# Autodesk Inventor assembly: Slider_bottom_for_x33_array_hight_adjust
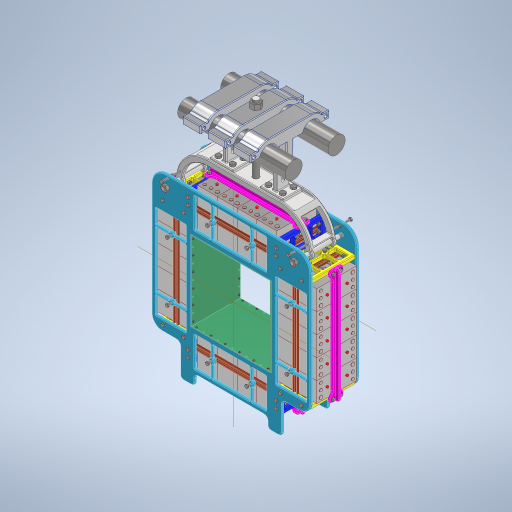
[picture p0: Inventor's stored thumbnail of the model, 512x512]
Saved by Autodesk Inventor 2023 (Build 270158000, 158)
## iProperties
Created: 2022-09
Part Number: Slider_bottom_for_x33_array_hight_adjust
Material: Aluminum 6061
Document SubType Name: Modeling
Designer: tornqvih
Mass: 680.873 g
Surface Area: 393.631 cm^2
Volume: 252.175 cm^3
Density: 2.7 g/cm^3
Appearance: Default
Sending System: Autodesk Inventor 2021
Preprocessor: ST-DEVELOPER v18.1
Title: C:\Users\Oleksii\Documents\Inventor\Scintillators_for_ISS\Part\ISSKUL9_v2.stp
Author: Oleksii
Part Number: Slider_bottom_for_x33_array
Mass: 854.06 g
Surface Area: 503.636 cm^2
Volume: 316.319 cm^3
Title: C:\Users\Oleksii\Documents\Inventor\Scintillators_for_ISS\Part\ISSKUL8_v2.stp
Created: 2023-10
Part Number: CeBr3Holder4x5
Document SubType Name: Assembly
Mass: 44866.1 g
Surface Area: 24623.5 cm^2
Volume: 16659.9 cm^3
Density: 2.69305 g/cm^3
Author: tornqvih
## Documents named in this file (31)
- \\Mac\Home\Documents\chalmers\Inventor2023\CeBr3Holder4x5\CeBr3Holder4x5.iam
- \\Mac\Home\Documents\chalmers\Inventor2023\CeBr3Holder4x5\FrontPlate.ipt
- \\Mac\Home\Documents\chalmers\Inventor2023\CeBr3Holder4x5\ShieldTop.ipt
- \\Mac\Home\Documents\chalmers\Inventor2023\CeBr3Holder4x5\ShieldLeft.ipt
- \\Mac\Home\Documents\chalmers\Inventor2023\CeBr3Holder4x5\SupportHorizontal.ipt
- \\Mac\Home\Documents\chalmers\Inventor2023\CeBr3Holder4x5\SupportVertical.ipt
- \\Mac\Home\Documents\chalmers\Inventor2023\CeBr3Holder4x5\BarHorizontal.ipt
- \\Mac\Home\Documents\chalmers\Inventor2023\CeBr3Holder4x5\BarVertical.ipt
- \\Mac\Home\Documents\chalmers\Inventor2023\CeBr3Holder4x5\CeBr3.ipt
- **\\Mac\Home\Documents\chalmers\Inventor2023\CeBr3Holder4x5\CeBr3Holder4x5.iam*LocalDocs*xAaaaqoaaAaaaaaaaAaaaqnqtPb*ISSKUL8_v2.ipt
- **\\Mac\Home\Documents\chalmers\Inventor2023\CeBr3Holder4x5\CeBr3Holder4x5.iam*LocalDocs*xAaaaarbaAaaaaaaaAaaaqtyoWc*ISSKUL9_v2.ipt
- \\Mac\Home\Documents\chalmers\Inventor2023\CeBr3Holder4x5\HangerSlide.ipt
- \\Mac\Home\Documents\chalmers\Inventor2023\CeBr3Holder4x5\ThreadedRod.ipt
- \\Mac\Home\Documents\Inventor\Content Center Files\R2023\en-US\AS 1112 (2)\AS 1112 - M10  Type 5.ipt
- \\Mac\Home\Documents\chalmers\Inventor2023\CeBr3Holder4x5\Roller.ipt
- \\Mac\Home\Documents\chalmers\Inventor2023\CeBr3Holder4x5\ThreadedHeight.ipt
- \\Mac\Home\Documents\Inventor\Content Center Files\R2023\en-US\AS 1112 (2)\AS 1112 - M16  Type 5.ipt
- \\Mac\Home\Documents\chalmers\Inventor2023\CeBr3Holder4x5\Hanger.ipt
- \\Mac\Home\Documents\chalmers\Inventor2023\CeBr3Holder4x5\U4.ipt
- \\Mac\Home\Documents\chalmers\Inventor2023\CeBr3Holder4x5\U5.ipt
- \\Mac\Home\Documents\chalmers\Inventor2023\CeBr3Holder4x5\U2.ipt
- \\Mac\Home\Documents\Inventor\Content Center Files\R2023\en-US\AS 1110\AS 1110 - M5 x 25.ipt
- \\Mac\Home\Documents\Inventor\Content Center Files\R2023\en-US\AS 1112 (2)\AS 1112 - M5  Type 5.ipt
- \\Mac\Home\Documents\Inventor\Content Center Files\R2023\en-US\AS 1427(05)\AS 1427 - M2.5 x 8(5) II.ipt
- \\Mac\Home\Documents\Inventor\Content Center Files\R2023\en-US\AS 1110\AS 1110 - M5 x 50.ipt
- \\Mac\Home\Documents\Inventor\Content Center Files\R2023\en-US\AS 1110\AS 1110 - M5 x 35.ipt
- \\Mac\Home\Documents\Inventor\Content Center Files\R2023\en-US\AS 1110\AS 1110 - M8 x 50.ipt
- \\Mac\Home\Documents\Inventor\Content Center Files\R2023\en-US\AS 1110\AS 1110 - M8 x 35.ipt
- \\Mac\Home\Documents\Inventor\Content Center Files\R2023\en-US\AS 1112 (2)\AS 1112 - M8  Type 5.ipt
- \\Mac\Home\Documents\chalmers\Inventor2023\ISSKUL_v2\ISSKUL8_v2.stp
- \\Mac\Home\Documents\chalmers\Inventor2023\ISSKUL_v2\ISSKUL9_v2.stp
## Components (281 placed, 47 different names)
1. FrontPlate
2. BackPlate
3. ShieldTop
4. ShieldBottom
5. ShieldLeft
6. ShieldRight
7. SupportHorizontalTR
8. SupportHorizontalTL
9. SupportHorizontalBL
10. SupportHorizontalBR
11. SupportVerticalTR
12. SupportVerticalTL
13. SupportVerticalBL
14. SupportVerticalBR
15. BarHorizontalTop — Mate:351, Mate:375, Mate:376
16. BarHorizontalBottom — Mate:350, Mate:377, Mate:378
17. BarVerticalRight — Mate:356, Mate:379, Mate:380
18. BarVerticalLeft — Mate:359, Mate:381, Mate:382
19. CeBr3:1 — Mate:138, Mate:139, Mate:140, Mate:143, Mate:151, Mate:351
20. CeBr3:2 — Mate:141, Mate:142, Mate:143, Mate:146, Mate:154
21. CeBr3:3 — Mate:144, Mate:145, Mate:146, Mate:149, Mate:157
22. CeBr3:4 — Mate:147, Mate:148, Mate:149, Mate:160, Mate:399
23. CeBr3:5 — Mate:150, Mate:151, Mate:152, Mate:155, Mate:391
24. CeBr3:6 — Mate:153, Mate:154, Mate:155, Mate:158
25. CeBr3:7 — Mate:156, Mate:157, Mate:158, Mate:161
26. CeBr3:8 — Mate:159, Mate:160, Mate:161
27. CeBr3:9 — Mate:162, Mate:163, Mate:164, Mate:167, Mate:175
28. CeBr3:10 — Mate:165, Mate:166, Mate:167, Mate:170, Mate:178
29. CeBr3:11 — Mate:168, Mate:169, Mate:170, Mate:173, Mate:181
30. CeBr3:12 — Mate:171, Mate:172, Mate:173, Mate:184, Mate:401
31. CeBr3:13 — Mate:174, Mate:175, Mate:176, Mate:179, Mate:393
32. CeBr3:14 — Mate:177, Mate:178, Mate:179, Mate:182
33. CeBr3:15 — Mate:180, Mate:181, Mate:182, Mate:185
34. CeBr3:16 — Mate:183, Mate:184, Mate:185, Mate:350
35. CeBr3:17 — Mate:186, Mate:187, Mate:188, Mate:191, Mate:202, Mate:359
36. CeBr3:18 — Mate:189, Mate:190, Mate:191, Mate:194, Mate:205
37. CeBr3:19 — Mate:192, Mate:193, Mate:194, Mate:197, Mate:208
38. CeBr3:20 — Mate:195, Mate:196, Mate:197, Mate:200, Mate:211
39. CeBr3:21 — Mate:198, Mate:199, Mate:200, Mate:214, Mate:405
40. CeBr3:22 — Mate:201, Mate:202, Mate:203, Mate:206, Mate:397
41. CeBr3:23 — Mate:204, Mate:205, Mate:206, Mate:209
42. CeBr3:24 — Mate:207, Mate:208, Mate:209, Mate:212
43. CeBr3:25 — Mate:210, Mate:211, Mate:212, Mate:215
44. CeBr3:26 — Mate:213, Mate:214, Mate:215
45. CeBr3:27 — Mate:216, Mate:217, Mate:218, Mate:221, Mate:232, Mate:356
46. CeBr3:28 — Mate:219, Mate:220, Mate:221, Mate:224, Mate:235
47. CeBr3:29 — Mate:222, Mate:223, Mate:224, Mate:227, Mate:238
48. CeBr3:30 — Mate:225, Mate:226, Mate:227, Mate:230, Mate:241
49. CeBr3:31 — Mate:228, Mate:229, Mate:230, Mate:244, Mate:403
50. CeBr3:32 — Mate:231, Mate:232, Mate:233, Mate:236, Mate:395
51. CeBr3:33 — Mate:234, Mate:235, Mate:236, Mate:239
52. CeBr3:34 — Mate:237, Mate:238, Mate:239, Mate:242
53. CeBr3:35 — Mate:240, Mate:241, Mate:242, Mate:245
54. CeBr3:36 — Mate:243, Mate:244, Mate:245
55. ThreadedRodRight — Mate:316, Flush:314, Mate:383, Angle:2
56. ThreadedRodLeft — Mate:317, Flush:315, Mate:384, Angle:3
57. AS 1112 (2) - Metric M10  Type 5:1
58. AS 1112 (2) - Metric M10  Type 5:2
59. AS 1112 (2) - Metric M10  Type 5:3
60. AS 1112 (2) - Metric M10  Type 5:4
61. Hanger:1
62. HangerSlideRight
63. HangerSlideLeft
64. ISSKUL8_v2:1 — Mate:315, Mate:334, Mate:338, Flush:316, Mate:341, Flush:317
65. ISSKUL8_v2:2 — Mate:314, Mate:333, Mate:336, Mate:339
66. ISSKUL9_v2:1 — Mate:337, Mate:340, Mate:373
67. RollerFront
68. RollerBack — Mate:339, Mate:340, Mate:341, Flush:317, Angle:1, Mate:362
69. ThreadedHeight:1 — Mate:373, Mate:388
70. U4Top — Mate:391, Mate:392, Mate:408, Mate:416, Mate:439, Mate:440
71. U4Bottom — Mate:393, Mate:394, Mate:410, Mate:422, Mate:445, Mate:446
72. U5Right — Mate:395, Mate:396, Mate:412, Mate:420, Mate:443, Mate:444
73. U5Left — Mate:397, Mate:398, Mate:414, Mate:418, Mate:441, Mate:442
74. U2Top — Mate:399, Mate:400, Mate:424, Mate:426, Mate:447, Mate:448
75. U2Bottom — Mate:401, Mate:402, Mate:436, Mate:438, Mate:449, Mate:450
76. U2Right — Mate:403, Mate:404, Mate:428, Mate:430, Mate:451, Mate:452
77. U2Left — Mate:405, Mate:406, Mate:432, Mate:434, Mate:453, Mate:454
78. AS 1110 - Metric M5 x 25:1
79. AS 1110 - Metric M5 x 25:12
80. AS 1110 - Metric M5 x 25:13
81. AS 1110 - Metric M5 x 25:14
82. AS 1110 - Metric M5 x 25:15
83. AS 1110 - Metric M5 x 25:16
84. AS 1110 - Metric M5 x 25:17
85. AS 1110 - Metric M5 x 25:18
86. AS 1110 - Metric M5 x 25:19
87. AS 1110 - Metric M5 x 25:20
88. AS 1110 - Metric M5 x 25:21
89. AS 1110 - Metric M5 x 25:22
90. AS 1110 - Metric M5 x 25:23
91. AS 1110 - Metric M5 x 25:24
92. AS 1110 - Metric M5 x 25:25
93. AS 1110 - Metric M5 x 25:26
94. AS 1110 - Metric M5 x 25:27
95. AS 1110 - Metric M5 x 25:38
96. AS 1110 - Metric M5 x 25:39
97. AS 1110 - Metric M5 x 25:40
98. AS 1110 - Metric M5 x 25:41
99. AS 1110 - Metric M5 x 25:42
100. AS 1110 - Metric M5 x 25:43
101. AS 1110 - Metric M5 x 25:44
102. AS 1110 - Metric M5 x 25:45
103. AS 1110 - Metric M5 x 25:46
104. AS 1110 - Metric M5 x 25:47
105. AS 1110 - Metric M5 x 25:48
106. AS 1110 - Metric M5 x 25:49
107. AS 1110 - Metric M5 x 25:50
108. AS 1110 - Metric M5 x 25:51
109. AS 1110 - Metric M5 x 25:52
110. AS 1112 (2) - Metric M5  Type 5:1
111. AS 1112 (2) - Metric M5  Type 5:2
112. AS 1112 (2) - Metric M5  Type 5:3
113. AS 1112 (2) - Metric M5  Type 5:4
114. AS 1112 (2) - Metric M5  Type 5:5
115. AS 1112 (2) - Metric M5  Type 5:6
116. AS 1112 (2) - Metric M5  Type 5:7
117. AS 1112 (2) - Metric M5  Type 5:8
118. AS 1112 (2) - Metric M5  Type 5:9
119. AS 1112 (2) - Metric M5  Type 5:10
120. AS 1112 (2) - Metric M5  Type 5:11
121. AS 1112 (2) - Metric M5  Type 5:12
122. AS 1112 (2) - Metric M5  Type 5:13
123. AS 1112 (2) - Metric M5  Type 5:14
124. AS 1112 (2) - Metric M5  Type 5:15
125. AS 1112 (2) - Metric M5  Type 5:16
126. AS 1112 (2) - Metric M5  Type 5:17
127. AS 1112 (2) - Metric M5  Type 5:18
128. AS 1112 (2) - Metric M5  Type 5:19
129. AS 1112 (2) - Metric M5  Type 5:20
130. AS 1112 (2) - Metric M5  Type 5:21
131. AS 1112 (2) - Metric M5  Type 5:22
132. AS 1112 (2) - Metric M5  Type 5:23
133. AS 1112 (2) - Metric M5  Type 5:24
134. AS 1112 (2) - Metric M5  Type 5:25
135. AS 1112 (2) - Metric M5  Type 5:26
136. AS 1112 (2) - Metric M5  Type 5:27
137. AS 1112 (2) - Metric M5  Type 5:28
138. AS 1112 (2) - Metric M5  Type 5:29
139. AS 1112 (2) - Metric M5  Type 5:30
140. AS 1112 (2) - Metric M5  Type 5:31
141. AS 1112 (2) - Metric M5  Type 5:32
142. AS 1427 H - Metric M2.5 x 8:1
143. AS 1427 H - Metric M2.5 x 8:2
144. AS 1427 H - Metric M2.5 x 8:3
145. AS 1427 H - Metric M2.5 x 8:4
146. AS 1427 H - Metric M2.5 x 8:5
147. AS 1427 H - Metric M2.5 x 8:6
148. AS 1427 H - Metric M2.5 x 8:7
149. AS 1427 H - Metric M2.5 x 8:8
150. AS 1427 H - Metric M2.5 x 8:9
151. AS 1427 H - Metric M2.5 x 8:10
152. AS 1427 H - Metric M2.5 x 8:11
153. AS 1427 H - Metric M2.5 x 8:12
154. AS 1427 H - Metric M2.5 x 8:13
155. AS 1427 H - Metric M2.5 x 8:14
156. AS 1427 H - Metric M2.5 x 8:15
157. AS 1427 H - Metric M2.5 x 8:16
158. AS 1427 H - Metric M2.5 x 8:17
159. AS 1427 H - Metric M2.5 x 8:18
160. AS 1427 H - Metric M2.5 x 8:19
161. AS 1427 H - Metric M2.5 x 8:20
162. AS 1427 H - Metric M2.5 x 8:21
163. AS 1427 H - Metric M2.5 x 8:22
164. AS 1427 H - Metric M2.5 x 8:23
165. AS 1427 H - Metric M2.5 x 8:24
166. AS 1427 H - Metric M2.5 x 8:25
167. AS 1427 H - Metric M2.5 x 8:26
168. AS 1427 H - Metric M2.5 x 8:27
169. AS 1427 H - Metric M2.5 x 8:28
170. AS 1427 H - Metric M2.5 x 8:29
171. AS 1427 H - Metric M2.5 x 8:30
172. AS 1427 H - Metric M2.5 x 8:31
173. AS 1427 H - Metric M2.5 x 8:32
174. AS 1427 H - Metric M2.5 x 8:33
175. AS 1427 H - Metric M2.5 x 8:34
176. AS 1427 H - Metric M2.5 x 8:35
177. AS 1427 H - Metric M2.5 x 8:36
178. AS 1427 H - Metric M2.5 x 8:37
179. AS 1427 H - Metric M2.5 x 8:38
180. AS 1427 H - Metric M2.5 x 8:39
181. AS 1427 H - Metric M2.5 x 8:40
182. AS 1427 H - Metric M2.5 x 8:41
183. AS 1427 H - Metric M2.5 x 8:42
184. AS 1427 H - Metric M2.5 x 8:43
185. AS 1427 H - Metric M2.5 x 8:44
186. AS 1427 H - Metric M2.5 x 8:45
187. AS 1427 H - Metric M2.5 x 8:46
188. AS 1427 H - Metric M2.5 x 8:47
189. AS 1427 H - Metric M2.5 x 8:48
190. AS 1110 - Metric M5 x 50:1 — Mate:455, Mate:456
191. AS 1110 - Metric M5 x 50:2 — Mate:457, Mate:458
192. AS 1110 - Metric M5 x 50:3 — Mate:459, Mate:460
193. AS 1110 - Metric M5 x 50:4 — Mate:461, Mate:462
194. AS 1110 - Metric M5 x 25:53 — Mate:407, Mate:408
195. AS 1110 - Metric M5 x 25:54 — Mate:409, Mate:410
196. AS 1110 - Metric M5 x 25:55 — Mate:411, Mate:412
197. AS 1110 - Metric M5 x 25:56 — Mate:413, Mate:414
198. AS 1110 - Metric M5 x 25:57 — Mate:415, Mate:416
199. AS 1110 - Metric M5 x 25:58 — Mate:417, Mate:418
200. AS 1110 - Metric M5 x 25:59 — Mate:419, Mate:420
201. AS 1110 - Metric M5 x 25:60 — Mate:421, Mate:422
202. AS 1110 - Metric M5 x 25:61 — Mate:424
203. AS 1110 - Metric M5 x 25:62 — Mate:425, Mate:426
204. AS 1110 - Metric M5 x 25:63 — Mate:427, Mate:428
205. AS 1110 - Metric M5 x 25:64 — Mate:429, Mate:430
206. AS 1110 - Metric M5 x 25:65 — Mate:431, Mate:432
207. AS 1110 - Metric M5 x 25:66 — Mate:433, Mate:434
208. AS 1110 - Metric M5 x 25:67 — Mate:435, Mate:436
209. AS 1110 - Metric M5 x 25:68 — Mate:437, Mate:438
210. AS 1112 (2) - Metric M5  Type 5:33 — Mate:439
211. AS 1112 (2) - Metric M5  Type 5:34 — Mate:440
212. AS 1112 (2) - Metric M5  Type 5:35 — Mate:443
213. AS 1112 (2) - Metric M5  Type 5:36 — Mate:444
214. AS 1112 (2) - Metric M5  Type 5:37 — Mate:441
215. AS 1112 (2) - Metric M5  Type 5:38 — Mate:442
216. AS 1112 (2) - Metric M5  Type 5:39 — Mate:445
217. AS 1112 (2) - Metric M5  Type 5:40 — Mate:446
218. AS 1112 (2) - Metric M5  Type 5:41 — Mate:447
219. AS 1112 (2) - Metric M5  Type 5:42 — Mate:448
220. AS 1112 (2) - Metric M5  Type 5:43 — Mate:451
221. AS 1112 (2) - Metric M5  Type 5:44 — Mate:452
222. AS 1112 (2) - Metric M5  Type 5:45 — Mate:453
223. AS 1112 (2) - Metric M5  Type 5:46 — Mate:454
224. AS 1112 (2) - Metric M5  Type 5:47 — Mate:450
225. AS 1112 (2) - Metric M5  Type 5:48 — Mate:449
226. AS 1110 - Metric M5 x 35:1
227. AS 1110 - Metric M5 x 35:2
228. AS 1110 - Metric M5 x 35:3
229. AS 1110 - Metric M5 x 35:4
230. AS 1110 - Metric M5 x 35:5
231. AS 1110 - Metric M5 x 35:6
232. AS 1110 - Metric M5 x 35:7
233. AS 1110 - Metric M5 x 35:8
234. AS 1110 - Metric M5 x 35:9
235. AS 1110 - Metric M5 x 35:10
236. AS 1110 - Metric M5 x 35:11
237. AS 1110 - Metric M5 x 35:12
238. AS 1110 - Metric M5 x 35:13
239. AS 1110 - Metric M5 x 35:14
240. AS 1110 - Metric M5 x 35:15
241. AS 1110 - Metric M5 x 35:16
242. AS 1112 (2) - Metric M5  Type 5:49
243. AS 1112 (2) - Metric M5  Type 5:50
244. AS 1112 (2) - Metric M5  Type 5:51
245. AS 1112 (2) - Metric M5  Type 5:52
246. AS 1112 (2) - Metric M5  Type 5:53
247. AS 1112 (2) - Metric M5  Type 5:54
248. AS 1112 (2) - Metric M5  Type 5:55
249. AS 1112 (2) - Metric M5  Type 5:56
250. AS 1112 (2) - Metric M5  Type 5:57
251. AS 1112 (2) - Metric M5  Type 5:58
252. AS 1112 (2) - Metric M5  Type 5:59
253. AS 1112 (2) - Metric M5  Type 5:60
254. AS 1112 (2) - Metric M5  Type 5:61
255. AS 1112 (2) - Metric M5  Type 5:62
256. AS 1112 (2) - Metric M5  Type 5:63
257. AS 1112 (2) - Metric M5  Type 5:64
258. AS 1112 (2) - Metric M5  Type 5:65
259. AS 1112 (2) - Metric M5  Type 5:66
260. AS 1112 (2) - Metric M5  Type 5:67
261. AS 1112 (2) - Metric M5  Type 5:68
262. AS 1110 - Metric M8 x 50:1
263. AS 1110 - Metric M8 x 50:2
264. AS 1110 - Metric M8 x 35:1
265. AS 1110 - Metric M8 x 35:2
266. AS 1110 - Metric M8 x 35:3
267. AS 1110 - Metric M8 x 35:4
268. AS 1110 - Metric M8 x 35:5
269. AS 1110 - Metric M8 x 35:6
270. AS 1110 - Metric M8 x 35:7
271. AS 1110 - Metric M8 x 35:8
272. AS 1112 (2) - Metric M8  Type 5:1
273. AS 1112 (2) - Metric M8  Type 5:2
274. AS 1112 (2) - Metric M8  Type 5:3
275. AS 1112 (2) - Metric M8  Type 5:4
276. AS 1112 (2) - Metric M8  Type 5:5
277. AS 1112 (2) - Metric M8  Type 5:6
278. AS 1112 (2) - Metric M8  Type 5:7
279. AS 1112 (2) - Metric M8  Type 5:8
280. AS 1112 (2) - Metric M16  Type 5:1
281. AS 1112 (2) - Metric M16  Type 5:2
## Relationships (215: Mate 208, Flush 4, Angle 3)
- Mate:138: CeBr3:1
- Mate:139: CeBr3:1
- Mate:140: CeBr3:1
- Mate:141: CeBr3:2
- Mate:142: CeBr3:2
- Mate:143: CeBr3:1 ↔ CeBr3:2
- Mate:144: CeBr3:3
- Mate:145: CeBr3:3
- Mate:146: CeBr3:2 ↔ CeBr3:3
- Mate:147: CeBr3:4
- Mate:148: CeBr3:4
- Mate:149: CeBr3:3 ↔ CeBr3:4
- Mate:150: CeBr3:5
- Mate:151: CeBr3:1 ↔ CeBr3:5
- Mate:152: CeBr3:5
- Mate:153: CeBr3:6
- Mate:154: CeBr3:2 ↔ CeBr3:6
- Mate:155: CeBr3:5 ↔ CeBr3:6
- Mate:156: CeBr3:7
- Mate:157: CeBr3:3 ↔ CeBr3:7
- Mate:158: CeBr3:6 ↔ CeBr3:7
- Mate:159: CeBr3:8
- Mate:160: CeBr3:4 ↔ CeBr3:8
- Mate:161: CeBr3:7 ↔ CeBr3:8
- Mate:162: CeBr3:9
- Mate:163: CeBr3:9
- Mate:164: CeBr3:9
- Mate:165: CeBr3:10
- Mate:166: CeBr3:10
- Mate:167: CeBr3:9 ↔ CeBr3:10
- Mate:168: CeBr3:11
- Mate:169: CeBr3:11
- Mate:170: CeBr3:10 ↔ CeBr3:11
- Mate:171: CeBr3:12
- Mate:172: CeBr3:12
- Mate:173: CeBr3:11 ↔ CeBr3:12
- Mate:174: CeBr3:13
- Mate:175: CeBr3:9 ↔ CeBr3:13
- Mate:176: CeBr3:13
- Mate:177: CeBr3:14
- Mate:178: CeBr3:10 ↔ CeBr3:14
- Mate:179: CeBr3:13 ↔ CeBr3:14
- Mate:180: CeBr3:15
- Mate:181: CeBr3:11 ↔ CeBr3:15
- Mate:182: CeBr3:14 ↔ CeBr3:15
- Mate:183: CeBr3:16
- Mate:184: CeBr3:12 ↔ CeBr3:16
- Mate:185: CeBr3:15 ↔ CeBr3:16
- Mate:186: CeBr3:17
- Mate:187: CeBr3:17
- Mate:188: CeBr3:17
- Mate:189: CeBr3:18
- Mate:190: CeBr3:18
- Mate:191: CeBr3:17 ↔ CeBr3:18
- Mate:192: CeBr3:19
- Mate:193: CeBr3:19
- Mate:194: CeBr3:18 ↔ CeBr3:19
- Mate:195: CeBr3:20
- Mate:196: CeBr3:20
- Mate:197: CeBr3:19 ↔ CeBr3:20
- Mate:198: CeBr3:21
- Mate:199: CeBr3:21
- Mate:200: CeBr3:20 ↔ CeBr3:21
- Mate:201: CeBr3:22
- Mate:202: CeBr3:17 ↔ CeBr3:22
- Mate:203: CeBr3:22
- Mate:204: CeBr3:23
- Mate:205: CeBr3:18 ↔ CeBr3:23
- Mate:206: CeBr3:22 ↔ CeBr3:23
- Mate:207: CeBr3:24
- Mate:208: CeBr3:19 ↔ CeBr3:24
- Mate:209: CeBr3:23 ↔ CeBr3:24
- Mate:210: CeBr3:25
- Mate:211: CeBr3:20 ↔ CeBr3:25
- Mate:212: CeBr3:24 ↔ CeBr3:25
- Mate:213: CeBr3:26
- Mate:214: CeBr3:21 ↔ CeBr3:26
- Mate:215: CeBr3:25 ↔ CeBr3:26
- Mate:216: CeBr3:27
- Mate:217: CeBr3:27
- Mate:218: CeBr3:27
- Mate:219: CeBr3:28
- Mate:220: CeBr3:28
- Mate:221: CeBr3:27 ↔ CeBr3:28
- Mate:222: CeBr3:29
- Mate:223: CeBr3:29
- Mate:224: CeBr3:28 ↔ CeBr3:29
- Mate:225: CeBr3:30
- Mate:226: CeBr3:30
- Mate:227: CeBr3:29 ↔ CeBr3:30
- Mate:228: CeBr3:31
- Mate:229: CeBr3:31
- Mate:230: CeBr3:30 ↔ CeBr3:31
- Mate:231: CeBr3:32
- Mate:232: CeBr3:27 ↔ CeBr3:32
- Mate:233: CeBr3:32
- Mate:234: CeBr3:33
- Mate:235: CeBr3:28 ↔ CeBr3:33
- Mate:236: CeBr3:32 ↔ CeBr3:33
- Mate:237: CeBr3:34
- Mate:238: CeBr3:29 ↔ CeBr3:34
- Mate:239: CeBr3:33 ↔ CeBr3:34
- Mate:240: CeBr3:35
- Mate:241: CeBr3:30 ↔ CeBr3:35
- Mate:242: CeBr3:34 ↔ CeBr3:35
- Mate:243: CeBr3:36
- Mate:244: CeBr3:31 ↔ CeBr3:36
- Mate:245: CeBr3:35 ↔ CeBr3:36
- Mate:314: ISSKUL8_v2:2
- Mate:315: ISSKUL8_v2:1
- Mate:316: ThreadedRodRight
- Flush:314: ThreadedRodRight
- Mate:317: ThreadedRodLeft
- Flush:315: ThreadedRodLeft
- Mate:333: ISSKUL8_v2:2
- Mate:334: ISSKUL8_v2:1
- Mate:336: ISSKUL8_v2:2
- Mate:337: ISSKUL9_v2:1
- Mate:338: ISSKUL8_v2:1
- Flush:316: ISSKUL8_v2:1
- Mate:339: ISSKUL8_v2:2 ↔ RollerBack
- Mate:340: ISSKUL9_v2:1 ↔ RollerBack
- Mate:341: ISSKUL8_v2:1 ↔ RollerBack
- Flush:317: ISSKUL8_v2:1 ↔ RollerBack
- Mate:350: BarHorizontalBottom ↔ CeBr3:16
- Mate:351: BarHorizontalTop ↔ CeBr3:1
- Mate:356: BarVerticalRight ↔ CeBr3:27
- Mate:359: BarVerticalLeft ↔ CeBr3:17
- Angle:1: RollerBack
- Mate:362: RollerBack
- Mate:373: ISSKUL9_v2:1 ↔ ThreadedHeight:1
- Mate:375: BarHorizontalTop
- Mate:376: BarHorizontalTop
- Mate:377: BarHorizontalBottom
- Mate:378: BarHorizontalBottom
- Mate:379: BarVerticalRight
- Mate:380: BarVerticalRight
- Mate:381: BarVerticalLeft
- Mate:382: BarVerticalLeft
- Mate:383: ThreadedRodRight
- Mate:384: ThreadedRodLeft
- Mate:388: ThreadedHeight:1
- Angle:2: ThreadedRodRight
- Angle:3: ThreadedRodLeft
- Mate:391: CeBr3:5 ↔ U4Top
- Mate:392: U4Top
- Mate:393: CeBr3:13 ↔ U4Bottom
- Mate:394: U4Bottom
- Mate:395: CeBr3:32 ↔ U5Right
- Mate:396: U5Right
- Mate:397: CeBr3:22 ↔ U5Left
- Mate:398: U5Left
- Mate:399: CeBr3:4 ↔ U2Top
- Mate:400: U2Top
- Mate:401: CeBr3:12 ↔ U2Bottom
- Mate:402: U2Bottom
- Mate:403: CeBr3:31 ↔ U2Right
- Mate:404: U2Right
- Mate:405: CeBr3:21 ↔ U2Left
- Mate:406: U2Left
- Mate:407: AS 1110 - Metric M5 x 25:53
- Mate:408: U4Top ↔ AS 1110 - Metric M5 x 25:53
- Mate:409: AS 1110 - Metric M5 x 25:54
- Mate:410: U4Bottom ↔ AS 1110 - Metric M5 x 25:54
- Mate:411: AS 1110 - Metric M5 x 25:55
- Mate:412: U5Right ↔ AS 1110 - Metric M5 x 25:55
- Mate:413: AS 1110 - Metric M5 x 25:56
- Mate:414: U5Left ↔ AS 1110 - Metric M5 x 25:56
- Mate:415: AS 1110 - Metric M5 x 25:57
- Mate:416: U4Top ↔ AS 1110 - Metric M5 x 25:57
- Mate:417: AS 1110 - Metric M5 x 25:58
- Mate:418: U5Left ↔ AS 1110 - Metric M5 x 25:58
- Mate:419: AS 1110 - Metric M5 x 25:59
- Mate:420: U5Right ↔ AS 1110 - Metric M5 x 25:59
- Mate:421: AS 1110 - Metric M5 x 25:60
- Mate:422: U4Bottom ↔ AS 1110 - Metric M5 x 25:60
- Mate:424: U2Top ↔ AS 1110 - Metric M5 x 25:61
- Mate:425: AS 1110 - Metric M5 x 25:62
- Mate:426: U2Top ↔ AS 1110 - Metric M5 x 25:62
- Mate:427: AS 1110 - Metric M5 x 25:63
- Mate:428: U2Right ↔ AS 1110 - Metric M5 x 25:63
- Mate:429: AS 1110 - Metric M5 x 25:64
- Mate:430: U2Right ↔ AS 1110 - Metric M5 x 25:64
- Mate:431: AS 1110 - Metric M5 x 25:65
- Mate:432: U2Left ↔ AS 1110 - Metric M5 x 25:65
- Mate:433: AS 1110 - Metric M5 x 25:66
- Mate:434: U2Left ↔ AS 1110 - Metric M5 x 25:66
- Mate:435: AS 1110 - Metric M5 x 25:67
- Mate:436: U2Bottom ↔ AS 1110 - Metric M5 x 25:67
- Mate:437: AS 1110 - Metric M5 x 25:68
- Mate:438: U2Bottom ↔ AS 1110 - Metric M5 x 25:68
- Mate:439: U4Top ↔ AS 1112 (2) - Metric M5  Type 5:33
- Mate:440: U4Top ↔ AS 1112 (2) - Metric M5  Type 5:34
- Mate:441: U5Left ↔ AS 1112 (2) - Metric M5  Type 5:37
- Mate:442: U5Left ↔ AS 1112 (2) - Metric M5  Type 5:38
- Mate:443: U5Right ↔ AS 1112 (2) - Metric M5  Type 5:35
- Mate:444: U5Right ↔ AS 1112 (2) - Metric M5  Type 5:36
- Mate:445: U4Bottom ↔ AS 1112 (2) - Metric M5  Type 5:39
- Mate:446: U4Bottom ↔ AS 1112 (2) - Metric M5  Type 5:40
- Mate:447: U2Top ↔ AS 1112 (2) - Metric M5  Type 5:41
- Mate:448: U2Top ↔ AS 1112 (2) - Metric M5  Type 5:42
- Mate:449: U2Bottom ↔ AS 1112 (2) - Metric M5  Type 5:48
- Mate:450: U2Bottom ↔ AS 1112 (2) - Metric M5  Type 5:47
- Mate:451: U2Right ↔ AS 1112 (2) - Metric M5  Type 5:43
- Mate:452: U2Right ↔ AS 1112 (2) - Metric M5  Type 5:44
- Mate:453: U2Left ↔ AS 1112 (2) - Metric M5  Type 5:45
- Mate:454: U2Left ↔ AS 1112 (2) - Metric M5  Type 5:46
- Mate:455: AS 1110 - Metric M5 x 50:1
- Mate:456: AS 1110 - Metric M5 x 50:1
- Mate:457: AS 1110 - Metric M5 x 50:2
- Mate:458: AS 1110 - Metric M5 x 50:2
- Mate:459: AS 1110 - Metric M5 x 50:3
- Mate:460: AS 1110 - Metric M5 x 50:3
- Mate:461: AS 1110 - Metric M5 x 50:4
- Mate:462: AS 1110 - Metric M5 x 50:4
## Named parameters: sa_0 = 0 mm, sa_2 = 0
